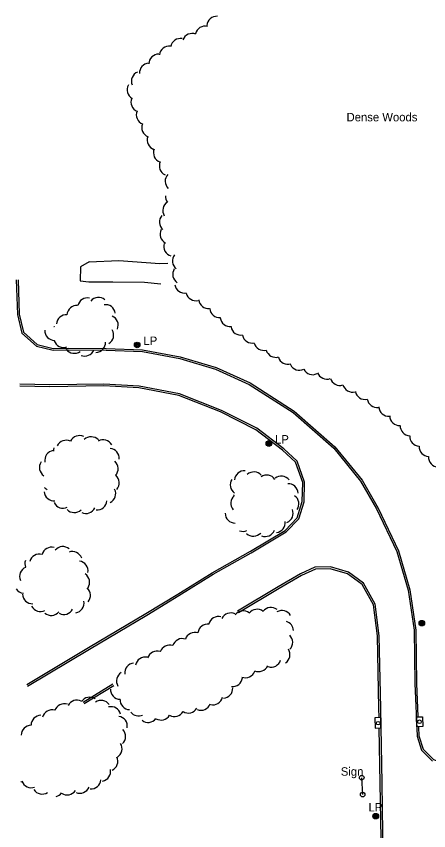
# Model space of a CAD drawing. Extents: x 2402803 to 2427059, y 6985292 to 6997652.
# Drawn here: x 2410157.7 to 2410392.4, y 6988683.9 to 6989146.9 of the extents above; entities that cross this region are included whole.
import ezdxf

# ---------------------------------------------------------------- set-up
doc = ezdxf.new("R2010")
doc.units = 0
for name, color, linetype in [('p_drainage conc drain', 7, 'Continuous'), ('p_road - paved curb', 7, 'Continuous'), ('p_road bridge end', 7, 'Continuous'), ('p_structure general', 7, 'Continuous'), ('p_structure sign', 7, 'Continuous'), ('p_utility manhole', 7, 'Continuous'), ('p_veg woods', 7, 'Continuous')]:
    doc.layers.add(name, color=color, linetype=linetype)

msp = doc.modelspace()

# ---------------------------------------------------------------- linework, layer by layer
at = {"layer": 'p_drainage conc drain'}
for points in [[(2410199.13, 6989007.4), (2410216.11, 6989008.17), (2410239.41, 6989006.46), (2410243.92, 6989006.66)], [(2410199.07, 6988995.92), (2410212.69, 6988996.02), (2410230.62, 6988995.79), (2410239.88, 6988994.8)]]:
    msp.add_lwpolyline(points, dxfattribs=at)
at = {"layer": 'p_road - paved curb'}
for points in [[(2410157.69, 6988997.07), (2410158.36, 6988977.43), (2410160.94, 6988966.72), (2410169.12, 6988959.43), (2410178.59, 6988957.06), (2410187.29, 6988957.29), (2410208.87, 6988957.03), (2410229.44, 6988956.37), (2410250.78, 6988952.37), (2410271.05, 6988946.22), (2410290.31, 6988937.64), (2410315.28, 6988921.58), (2410338.3, 6988901.38), (2410353.64, 6988882.71), (2410362.64, 6988866.81), (2410374.2, 6988842.64), (2410380.61, 6988820.58), (2410384.07, 6988797.89), (2410384.44, 6988767.61), (2410385.76, 6988737.72), (2410388.27, 6988729.73), (2410394.59, 6988723.42)], [(2410158.69, 6988997.1), (2410159.36, 6988977.57), (2410161.84, 6988967.26), (2410169.6, 6988960.34), (2410178.7, 6988958.06), (2410187.28, 6988958.29), (2410208.89, 6988958.03), (2410229.55, 6988957.37), (2410251.02, 6988953.34), (2410271.4, 6988947.16), (2410290.79, 6988938.52), (2410315.88, 6988922.38), (2410339.02, 6988902.08), (2410354.47, 6988883.28), (2410363.53, 6988867.27), (2410375.14, 6988843), (2410381.59, 6988820.8), (2410385.07, 6988797.97), (2410385.44, 6988767.64), (2410386.27, 6988748.89)], [(2410386.53, 6988742.79), (2410386.75, 6988737.89), (2410389.15, 6988730.26), (2410395.15, 6988724.28), (2410401.95, 6988721.68), (2410410.9, 6988721.06), (2410451.33, 6988721.58), (2410485.65, 6988721.93), (2410529.52, 6988721.85), (2410536.78, 6988722.38), (2410544.13, 6988725.67), (2410548.43, 6988730.61), (2410551.05, 6988740.61), (2410549.21, 6988766.42), (2410543.07, 6988816.46), (2410535.97, 6988863.3), (2410527.08, 6988913.23), (2410516.74, 6988957.93)], [(2410163.62, 6988766.97), (2410198.77, 6988788), (2410231.48, 6988807.33), (2410249.7, 6988818.45), (2410269.13, 6988830.53), (2410290.88, 6988842.8), (2410310.73, 6988854.62), (2410317.56, 6988861.72), (2410320.46, 6988870.98), (2410320.77, 6988881.83), (2410316.59, 6988893.35), (2410309.21, 6988900.16), (2410294.09, 6988911.86), (2410273.98, 6988921.97), (2410250.24, 6988931.37), (2410227.46, 6988935.71), (2410207.51, 6988936.82), (2410176.79, 6988936.31), (2410159.78, 6988936.71)], [(2410164.13, 6988766.11), (2410199.28, 6988787.14), (2410231.99, 6988806.47), (2410250.22, 6988817.6), (2410269.64, 6988829.67), (2410291.38, 6988841.93), (2410311.36, 6988853.83), (2410318.44, 6988861.2), (2410321.46, 6988870.81), (2410321.77, 6988881.99), (2410317.45, 6988893.92), (2410309.86, 6988900.92), (2410294.63, 6988912.71), (2410274.39, 6988922.88), (2410250.52, 6988932.33), (2410227.58, 6988936.7), (2410207.53, 6988937.82), (2410176.79, 6988937.31), (2410159.8, 6988937.71)], [(2410366.53, 6988668.78), (2410365.82, 6988710.97), (2410365.05, 6988753.6), (2410364.18, 6988794.67), (2410361.92, 6988812.65), (2410355.33, 6988824.58), (2410346.71, 6988830.82), (2410336.46, 6988833.84), (2410327.65, 6988833.63), (2410319.46, 6988829.85), (2410306.75, 6988822.47), (2410283.61, 6988808.64)], [(2410364.15, 6988748.22), (2410364.05, 6988753.58), (2410363.18, 6988794.6), (2410360.95, 6988812.33), (2410354.56, 6988823.9), (2410346.26, 6988829.91), (2410336.33, 6988832.84), (2410327.88, 6988832.64), (2410319.92, 6988828.96), (2410307.26, 6988821.61), (2410284.12, 6988807.78)], [(2410212.69, 6988767.13), (2410195.76, 6988756.85)], [(2410213.21, 6988766.28), (2410196.28, 6988756)], [(2410374.02, 6988490.33), (2410371.48, 6988508.59), (2410369.08, 6988543.28), (2410367.26, 6988586.22), (2410366.34, 6988627.02), (2410365.53, 6988668.76), (2410364.82, 6988710.95), (2410364.26, 6988742.14)]]:
    msp.add_lwpolyline(points, dxfattribs=at)
at = {"layer": 'p_road bridge end'}
msp.add_lwpolyline([(2410199.13, 6989007.4), (2410194.2, 6989004.54), (2410194, 6988996.52), (2410199.07, 6988995.92)], dxfattribs=at)
for points in [[(2410365.15, 6988742.33), (2410365.05, 6988748.16), (2410361.8, 6988748.1), (2410361.9, 6988742.27)], [(2410385.63, 6988742.98), (2410385.38, 6988748.54), (2410388.85, 6988748.7), (2410389.1, 6988743.14)]]:
    msp.add_lwpolyline(points, close=True, dxfattribs=at)
at = {"layer": 'p_structure general'}
for centre in [(2410363.6, 6988745.05), (2410387.18, 6988745.82)]:
    msp.add_circle(centre, 1, dxfattribs=at)
at = {"layer": 'p_structure sign'}
msp.add_line((2410354.82, 6988704.39), (2410354.28, 6988714), dxfattribs=at)
for centre in [(2410354.27, 6988714.01), (2410354.81, 6988704.4)]:
    msp.add_circle(centre, 1.3, dxfattribs=at)
at = {"layer": 'p_utility manhole'}
for centre, radius in [((2410226.49, 6988960.06), 1.6), ((2410226.49, 6988960.06), 1.3), ((2410226.49, 6988960.06), 1), ((2410226.49, 6988960.06), 0.539), ((2410226.49, 6988960.06), 0.192), ((2410301.4, 6988904), 1.6), ((2410301.4, 6988904), 1.3), ((2410301.4, 6988904), 1), ((2410301.4, 6988904), 0.539), ((2410301.4, 6988904), 0.192), ((2410388.48, 6988801.87), 1.6), ((2410388.48, 6988801.87), 1.3), ((2410388.48, 6988801.87), 1), ((2410388.48, 6988801.87), 0.539), ((2410388.48, 6988801.87), 0.192), ((2410362.25, 6988692.15), 1.6), ((2410362.25, 6988692.15), 1.3), ((2410362.25, 6988692.15), 1), ((2410362.25, 6988692.15), 0.539), ((2410362.25, 6988692.15), 0.192)]:
    msp.add_circle(centre, radius, dxfattribs=at)
at = {"layer": 'p_veg woods'}
for centre, start, end in [((2410271.71, 6989141.29), 85.6804, 175.6804), ((2410265.16, 6989135.67), 76.2552, 166.2552), ((2410251.12, 6989128.68), 79.5209, 169.5209), ((2410257.77, 6989131.51), 68.6591, 158.6591), ((2410244.73, 6989124.28), 82.7198, 172.7198), ((2410238.76, 6989119.78), 88.9396, 178.9396), ((2410233.5, 6989114.73), 94.0972, 184.0972), ((2410228.84, 6989110.03), 112.4111, 202.4111), ((2410226.4, 6989105.12), 150.5745, 240.5745), ((2410228.61, 6989098.16), 157.8585, 247.8585), ((2410231.65, 6989090.96), 158.088, 248.088), ((2410234.74, 6989083.69), 158.3368, 248.3368), ((2410237.81, 6989076.61), 160.9114, 250.9114), ((2410241.39, 6989069.39), 158.7959, 248.7959), ((2410244.75, 6989061.82), 154.6914, 244.6914), ((2410248.08, 6989053.18), 136.4749, 226.4749), ((2410246.72, 6989036.55), 122.0967, 212.0967), ((2410248.26, 6989044.52), 176.3899, 215.3276), ((2410244.79, 6989029.99), 139.0075, 229.0075), ((2410245.2, 6989022.99), 152.1719, 242.1719), ((2410247.25, 6989016.1), 163.4463, 253.4463), ((2410252.22, 6989007.86), 142.2173, 232.2173), ((2410252.34, 6989000.22), 147.249, 237.249), ((2410253.52, 6988995.18), 189.4351, 279.4351), ((2410198.19, 6988981.2), 77.675, 167.675), ((2410204.51, 6988981.42), 50.5179, 140.5179), ((2410259.88, 6988990.86), 193.7261, 283.726), ((2410267.13, 6988986.34), 186.1071, 276.1071), ((2410192.19, 6988976.89), 86.2092, 176.2092), ((2410208.44, 6988977.33), 8.1698, 98.1698), ((2410273.39, 6988981.26), 185.1972, 275.1972), ((2410186.17, 6988971.63), 86.2092, 176.2092), ((2410210.03, 6988971.34), 336.4472, 66.4472), ((2410279.41, 6988976.15), 186.6851, 276.6851), ((2410179.5, 6988968.31), 179.3065, 269.3065), ((2410183.51, 6988974.14), 218.5291, 220.6995), ((2410207.47, 6988965.81), 300.2583, 30.2583), ((2410285.48, 6988971.29), 189.9379, 279.9379), ((2410184.63, 6988964.28), 199.1316, 289.1316), ((2410291.87, 6988966.82), 192.88, 282.88), ((2410190.69, 6988960.98), 216.4477, 306.4477), ((2410202.82, 6988961.51), 272.2827, 2.2827), ((2410298.5, 6988962.63), 195.1751, 285.1751), ((2410196.63, 6988959.38), 248.4398, 338.4398), ((2410305.35, 6988958.65), 196.2317, 286.2317), ((2410312.26, 6988954.78), 197.3929, 287.3929), ((2410318.84, 6988951.34), 205.8028, 295.8028), ((2410326.33, 6988948.8), 207.0758, 297.0758), ((2410334.43, 6988946.22), 200.153, 290.153), ((2410341.82, 6988942.7), 197.4799, 287.4799), ((2410349.07, 6988938.87), 194.6032, 284.6032), ((2410356.21, 6988934.7), 190.8422, 280.8422), ((2410363, 6988930.14), 188.302, 278.302), ((2410369.66, 6988925.21), 184.2741, 274.2741), ((2410375.85, 6988919.85), 181.6385, 271.6385), ((2410381.81, 6988914.09), 177.8552, 267.4362), ((2410193.58, 6988902.87), 63.7817, 153.7817), ((2410200.28, 6988902.21), 43.3259, 133.3259), ((2410387.23, 6988908.16), 177.0059, 267.0059), ((2410186.13, 6988900.25), 65.2025, 155.2025), ((2410207.1, 6988900.45), 29.3061, 119.3061), ((2410392.56, 6988902.23), 177.2604, 267.2604), ((2410179.56, 6988894.43), 99.7893, 189.7893), ((2410184.58, 6988900.36), 167.4219, 186.436), ((2410210.63, 6988895.63), 355.7485, 85.7485), ((2410176.5, 6988890.44), 146.523, 236.523), ((2410210, 6988889.71), 318.1327, 48.1327), ((2410397.92, 6988896.34), 177.8601, 267.8601), ((2410287.54, 6988882.9), 85.7317, 175.7317), ((2410210.64, 6988881.68), 318.9584, 48.9584), ((2410285.08, 6988880.48), 145.7794, 235.7794), ((2410292.88, 6988882.22), 41.3079, 131.3079), ((2410300.22, 6988880.46), 34.4789, 124.4789), ((2410308.46, 6988879.81), 38.1639, 128.1639), ((2410177.58, 6988883.06), 224.9108, 244.9031), ((2410312.48, 6988875.49), 3.1465, 93.1465), ((2410179.24, 6988877.08), 184.4035, 274.4035), ((2410208.61, 6988875.49), 296.6086, 26.6086), ((2410285.4, 6988870.16), 131.985, 221.985), ((2410285.82, 6988878.14), 215.4866, 221.985), ((2410312.83, 6988869.7), 324.8054, 54.8054), ((2410184.26, 6988872.88), 206.0006, 296.0006), ((2410203.68, 6988871.87), 265.4786, 355.4786), ((2410190.7, 6988870.43), 222.9532, 312.9532), ((2410197.25, 6988869.87), 245.4294, 335.4294), ((2410309.6, 6988864.39), 292.1661, 22.1661), ((2410282.22, 6988864.46), 180.4242, 270.4242), ((2410305.11, 6988859.05), 276.5337, 6.5337), ((2410286.66, 6988859.68), 250.1071, 293.8605), ((2410292.63, 6988856.97), 227.122, 317.122), ((2410299.32, 6988856.8), 248.1428, 338.1428), ((2410177.78, 6988839.44), 74.4599, 164.4599), ((2410184.2, 6988839.77), 50.1966, 140.1966), ((2410189.58, 6988836.96), 19.5093, 109.5093), ((2410168.22, 6988835.83), 161.7626, 202.9784), ((2410170.82, 6988835.5), 74.4599, 164.4599), ((2410165.22, 6988828.41), 112.9784, 202.9784), ((2410192.89, 6988831.53), 351.9595, 81.9595), ((2410193.8, 6988825.11), 327.0841, 57.0841), ((2410162.47, 6988824.45), 212.5529, 262.2554), ((2410194.24, 6988817.66), 319.0802, 49.0802), ((2410166.82, 6988818.57), 182.5885, 272.5885), ((2410190.61, 6988813.32), 280.0089, 10.0089), ((2410171.49, 6988814.11), 206.3314, 296.3314), ((2410184.75, 6988812.48), 242.0677, 332.0677), ((2410294.7, 6988804.11), 52.1743, 142.1743), ((2410302.53, 6988805.15), 51.2978, 141.2978), ((2410177.56, 6988811.93), 230.1979, 320.1979), ((2410272.71, 6988800.01), 75.0654, 165.0654), ((2410279.71, 6988802.02), 63.8459, 153.8459), ((2410286.84, 6988803.16), 52.7992, 142.7992), ((2410308.88, 6988803.41), 30.0469, 120.0469), ((2410266.62, 6988795.7), 82.206, 172.206), ((2410309.81, 6988797.34), 4.385, 72.6351), ((2410259.26, 6988791.01), 71.0915, 161.0915), ((2410252.17, 6988787.45), 72.0746, 162.0746), ((2410309.33, 6988791), 315.417, 45.417), ((2410245.01, 6988783.77), 71.2899, 161.2899), ((2410307.78, 6988783.99), 303.1337, 33.1337), ((2410231.1, 6988776.96), 78.6448, 168.6448), ((2410237.82, 6988780.34), 71.7485, 161.7484), ((2410225.07, 6988773.57), 96.0635, 186.0635), ((2410295.6, 6988779.96), 246.0955, 336.0955), ((2410302.75, 6988782.55), 252.0101, 342.01), ((2410220.34, 6988768.99), 120.9742, 210.9742), ((2410288.14, 6988776.52), 249.1707, 339.1707), ((2410280.73, 6988771.49), 263.4503, 353.4503), ((2410216.95, 6988764.22), 177.8398, 267.8398), ((2410275.2, 6988764.8), 273.6371, 3.6371), ((2410199.47, 6988754.12), 55.9014, 145.9014), ((2410222.39, 6988758.35), 177.8398, 267.8398), ((2410269.49, 6988761.09), 256.8567, 346.8567), ((2410184.97, 6988750.4), 70.9609, 160.9609), ((2410192.19, 6988752.47), 63.5393, 153.5393), ((2410206.04, 6988752.32), 35.7918, 125.7918), ((2410211.59, 6988748.74), 14.0112, 104.0112), ((2410262.75, 6988757.97), 248.8527, 338.8527), ((2410171.74, 6988743.85), 90.2984, 180.2984), ((2410178.13, 6988746.92), 75.4442, 165.4442), ((2410227.27, 6988754.79), 219.2354, 294.2135), ((2410240.05, 6988752.44), 239.4746, 329.4746), ((2410247.8, 6988754.44), 239.4683, 329.4683), ((2410255.54, 6988756.43), 239.4278, 329.4278), ((2410215.24, 6988743.31), 351.062, 81.062), ((2410232.75, 6988751.1), 231.6543, 321.6543), ((2410166.12, 6988738.17), 90.2984, 180.2984), ((2410214.23, 6988737.46), 313.6546, 43.6546), ((2410212.25, 6988730.51), 301.672, 31.672), ((2410209.8, 6988723.32), 295.8035, 25.8035), ((2410205.74, 6988717.6), 280.8618, 10.8618), ((2410200.23, 6988713.27), 265.4744, 355.4744), ((2410158.64, 6988716.98), 286.0683, 292.6094), ((2410166.26, 6988713.96), 199.5667, 289.5667), ((2410193.92, 6988710.84), 246.7613, 336.7613), ((2410172.47, 6988710.32), 212.5009, 302.5009), ((2410179.02, 6988708.86), 284.9455, 321.8291), ((2410186.65, 6988709.85), 236.2126, 326.2126)]:
    msp.add_arc(centre, 5.65, start, end, dxfattribs=at)

# ---------------------------------------------------------------- texts
at = {"layer": 'p_structure sign'}
msp.add_text('Sign', height=4.8, dxfattribs=at).set_placement((2410342.35, 6988715.15))
at = {"layer": 'p_utility manhole'}
for p in [(2410226.49, 6988960.06), (2410301.4, 6988904), (2410354.57, 6988694.83)]:
    msp.add_text('  LP', height=4.8, dxfattribs=at).set_placement(p)
at = {"layer": 'p_veg woods'}
msp.add_text('Dense Woods', height=4.8, dxfattribs=at).set_placement((2410345.64, 6989087.21))

doc.saveas('drawing.dxf')
